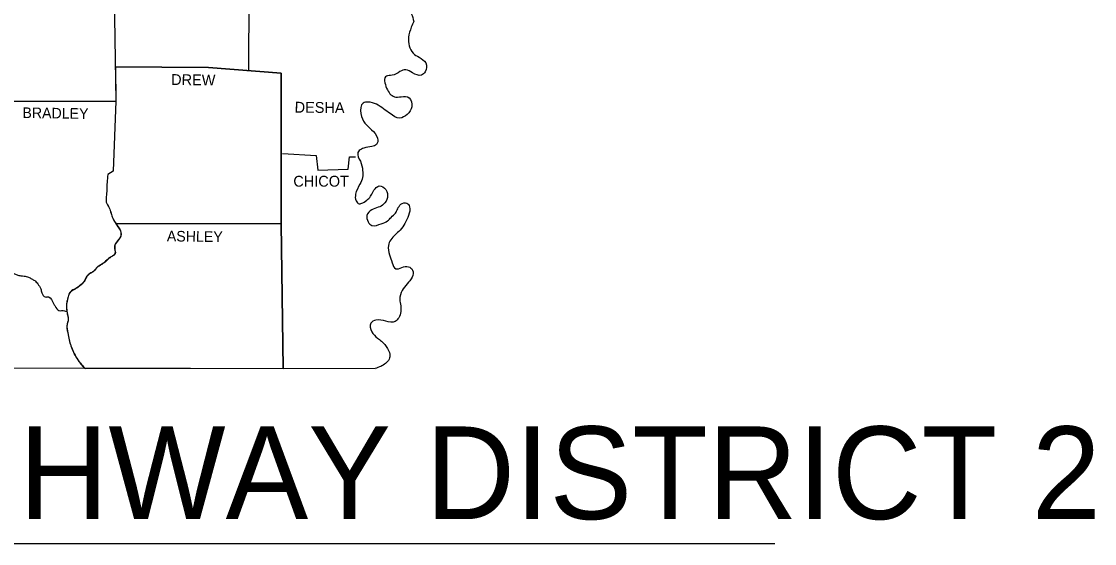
# Model space of a CAD drawing. Extents: x -42408 to 34530, y -43140 to 20491.
# Drawn here: x 9102 to 11234, y 6993 to 8031 of the extents above; entities that cross this region are included whole.
import ezdxf

# ---------------------------------------------------------------- set-up
doc = ezdxf.new("R2010")
doc.units = 0
for name, color, linetype in [('1', 7, 'Continuous'), ('2', 7, 'Continuous'), ('S_MISC_BOUNDARY', 7, 'Continuous')]:
    doc.layers.add(name, color=color, linetype=linetype)

msp = doc.modelspace()

# ---------------------------------------------------------------- linework, layer by layer
at = {"layer": '1'}
for points in [[(9297, 8143.5), (9297.5, 8080.9), (9286.9, 8080.4), (9289.9, 7872.6)], [(9635.4, 8116.9), (9629.4, 8103.4), (9602.9, 8100.9), (9601.4, 8082.9), (9553.8, 8082.9), (9553.3, 7933.2)], [(9288.4, 7940.7), (9474.2, 7939.2), (9618.4, 7928.2)], [(9618.4, 7928.2), (9618.4, 7628.8), (9622.4, 7340.9)], [(9063.6, 7872.1), (9289.9, 7872.6)], [(9289.9, 7872.6), (9284.9, 7733.4), (9273.9, 7726.4)], [(9620.9, 7768.5), (9688, 7764.4), (9691, 7735.4), (9751.6, 7737.4), (9754.1, 7761.9), (9765.6, 7761.9)], [(7969.2, 7748.9), (7970.2, 7343.9), (9805.1, 7340.9)], [(9293, 7629.3), (9618.4, 7629.3)]]:
    msp.add_lwpolyline(points, dxfattribs=at)
for points in [[(10226.7, 8693.2), (10215.2, 8678.7), (10198.2, 8687.7), (10198.2, 8699.7), (10200.7, 8712.2), (10194.7, 8720.2), (10184.1, 8716.7), (10184.1, 8701.2), (10183.1, 8686.2), (10180.1, 8664.6), (10187.1, 8658.1), (10203.2, 8656.1), (10214.7, 8653.1), (10221.7, 8641.6), (10221.2, 8627.6), (10215.7, 8614.1), (10207.7, 8603.1), (10195.2, 8599.1), (10185.1, 8605.6), (10181.1, 8618.6), (10176.6, 8630.1), (10168.1, 8638.6), (10159.1, 8629.1), (10157.1, 8611.6), (10157.6, 8596.6), (10157.6, 8576), (10170.6, 8562.5), (10178.6, 8547), (10176.1, 8533), (10166.6, 8516.5), (10162.6, 8501.9), (10158.6, 8482.4), (10159.1, 8460.9), (10155.6, 8439.8), (10148.6, 8425.8), (10135.6, 8414.3), (10127.1, 8406.8), (10120.1, 8399.3), (10116.6, 8384.3), (10114, 8373.8), (10104.5, 8361.2), (10097, 8360.2), (10091, 8365.3), (10089, 8373.8), (10089, 8382.3), (10085, 8390.8), (10072.5, 8394.3), (10062.5, 8393.8), (10058, 8386.8), (10064.5, 8367.3), (10067, 8354.7), (10063.5, 8337.7), (10065.5, 8335.7), (10047.5, 8326.2), (10032.9, 8324.7), (10020.9, 8321.2), (10009.4, 8313.7), (10003.9, 8302.7), (9995.9, 8293.7), (9988.9, 8285.1), (9979.4, 8281.1), (9968.9, 8283.1), (9954.8, 8284.6), (9946.8, 8274.6), (9949.3, 8260.1), (9958.8, 8251.6), (9972.9, 8247.6), (9987.4, 8248.6), (10001.4, 8250.1), (10014.4, 8243.1), (10011.9, 8229.6), (9999.4, 8223.1), (9980.9, 8221.1), (9965.8, 8222.6), (9947.8, 8218.6), (9938.8, 8207), (9943.8, 8189.5), (9963.3, 8182.5), (9972.4, 8166), (9972.9, 8150.5), (9966.4, 8129.9), (9957.3, 8120.4), (9939.8, 8116.4), (9926.3, 8113.9), (9924.3, 8090.9), (9918.3, 8079.4), (9907.8, 8075.9), (9892.8, 8083.4), (9883.7, 8086.9), (9872.7, 8091.9), (9858.7, 8100.4), (9848.2, 8098.9), (9851.2, 8076.9), (9852.2, 8075.9), (9864.2, 8059.3), (9876.2, 8046.3), (9881.7, 8030.8)], [(9881.7, 8030.8), (9876.7, 8019.3), (9871.2, 7999.3), (9872.7, 7982.2), (9880.2, 7967.7), (9892.3, 7959.7), (9905.3, 7948.2), (9904.3, 7930.7), (9896.8, 7924.2), (9879.2, 7928.7), (9865.7, 7934.7), (9854.2, 7931.2), (9838.7, 7923.7), (9827.2, 7922.2), (9827.7, 7898.1), (9843.2, 7881.1), (9856.7, 7881.1), (9872.2, 7879.1), (9877.7, 7861.1), (9868.7, 7846.1), (9853.7, 7838.5), (9834.7, 7847.6), (9821.2, 7857.1), (9807.6, 7866.1), (9790.6, 7870.6), (9781.1, 7868.6), (9776.6, 7847.6), (9784.6, 7828.5), (9797.6, 7815.5), (9809.6, 7798.5), (9807.6, 7786), (9798.6, 7782.5), (9782.6, 7779), (9773.1, 7774), (9770.6, 7770), (9775.6, 7752.9), (9780.1, 7734.4), (9780.1, 7720.4), (9774.6, 7707.4), (9766.1, 7687.3), (9767.1, 7674.3), (9773.1, 7668.3), (9780.6, 7670.3), (9790.6, 7677.3), (9797.1, 7685.3), (9802.6, 7695.4), (9813.1, 7703.9), (9826.2, 7696.4), (9829.2, 7680.8), (9821.7, 7667.3), (9811.1, 7661.3), (9798.1, 7656.3), (9788.6, 7645.3), (9791.1, 7632.3), (9798.6, 7625.3), (9817.2, 7628.8), (9829.7, 7634.3), (9836.7, 7641.3), (9845.2, 7649.8), (9849.7, 7658.3), (9856.2, 7667.3), (9867.7, 7669.8), (9873.2, 7662.3), (9871.2, 7645.3), (9864.2, 7629.3), (9854.7, 7615.8), (9844.2, 7606.2), (9831.2, 7585.7), (9833.7, 7566.7), (9838.7, 7551.2), (9845.7, 7539.1), (9857.7, 7541.7), (9871.2, 7543.2), (9879.2, 7536.6), (9878.2, 7522.6), (9868.2, 7509.1), (9858.7, 7496.1), (9853.7, 7478.1), (9855.7, 7465.6), (9855.7, 7454), (9851.7, 7441.5), (9844.7, 7434.5), (9826.2, 7435), (9806.6, 7437), (9796.1, 7431), (9798.1, 7414), (9809.6, 7401.5), (9817.7, 7395), (9829.2, 7380.9), (9834.2, 7369.4), (9832.7, 7359.4), (9825.7, 7350.9), (9805.1, 7340.9)], [(9273.9, 7726.4), (9272.4, 7710.9), (9271.9, 7696.4), (9270.9, 7682.3), (9270.9, 7671.8), (9276.9, 7660.3), (9280.4, 7649.3), (9283.9, 7639.8), (9290.9, 7627.3), (9297.5, 7617.8), (9299.5, 7604.2), (9295.5, 7597.2), (9287.9, 7586.7), (9287.4, 7567.7), (9278.4, 7561.7), (9266.9, 7551.7), (9260.4, 7547.2), (9253.4, 7542.7), (9245.9, 7534.6), (9234.9, 7527.1), (9226.9, 7514.6), (9217.9, 7505.1), (9210.3, 7500.1), (9199.8, 7493.6), (9195.3, 7483.6), (9191.8, 7465), (9193.3, 7451.5), (9195.3, 7439.5), (9192.8, 7424.5), (9195.3, 7408), (9197.8, 7395), (9201.8, 7383.4), (9207.3, 7370.4), (9214.3, 7358.4), (9229.4, 7339.9)], [(8774.8, 7610.7), (8782.8, 7616.3), (8790.3, 7619.3), (8797.8, 7617.8), (8805.8, 7616.8), (8812.8, 7617.8), (8821.8, 7616.3), (8829.3, 7611.7), (8837.8, 7608.2), (8846.4, 7608.2), (8853.9, 7608.2), (8860.4, 7603.7), (8872.4, 7604.2), (8882.4, 7608.2), (8892.4, 7611.2), (8905.9, 7612.7), (8918, 7604.2), (8926.5, 7597.2), (8933.5, 7589.2), (8938.5, 7580.2), (8944, 7575.2), (8953, 7571.7), (8960, 7570.2), (8968.5, 7567.7), (8973, 7565.7), (8977, 7556.2), (8983.5, 7543.2), (8996.1, 7538.6), (9011.6, 7544.7), (9024.1, 7548.2), (9033.1, 7551.2), (9038.6, 7553.2), (9043.6, 7553.7), (9042.1, 7554.7), (9048.1, 7556.2), (9053.6, 7552.2), (9057.1, 7546.7), (9063.1, 7538.6), (9068.7, 7531.6), (9074.2, 7529.1), (9079.7, 7532.1), (9087.2, 7529.6), (9093.7, 7527.1), (9101.2, 7525.1), (9107.7, 7524.6), (9116.2, 7522.6), (9122.7, 7519.1), (9128.7, 7515.6), (9134.7, 7509.1), (9140.7, 7499.1), (9142.8, 7491.1), (9149.8, 7483.1), (9156.3, 7483.1), (9165.8, 7470.1), (9169.3, 7465), (9176.8, 7456), (9182.3, 7456), (9192.8, 7454)]]:
    msp.add_spline(points, degree=3, dxfattribs=at)
at = {"layer": '2'}
msp.add_line((7249.3, 6992.9), (10598.6, 6992.9), dxfattribs=at)
at = {"layer": 'S_MISC_BOUNDARY'}
for p, q in [((9289, 7940.7), (9289.9, 7872.6)), ((9618.4, 7629.3), (9618.4, 7928.2)), ((9289.7, 7629.3), (9618.4, 7629.3)), ((9618.4, 7628.8), (9289.7, 7628.8)), ((9622.4, 7340.7), (9618.4, 7628.8)), ((9227.5, 7341.3), (9622.4, 7340.7))]:
    msp.add_line(p, q, dxfattribs=at)
for points in [[(9618.4, 7928.2), (9474.2, 7939.2), (9289, 7940.7)], [(9289.9, 7872.6), (9284.9, 7733.4), (9273.9, 7726.4)]]:
    msp.add_lwpolyline(points, dxfattribs=at)
for points in [[(9273.9, 7726.4), (9272.4, 7710.9), (9271.9, 7696.4), (9270.9, 7682.3), (9270.6, 7677.1), (9270.7, 7674.4), (9270.9, 7671.8), (9271.9, 7668.8), (9273.6, 7666), (9275.5, 7663.2), (9276.9, 7660.3), (9280.4, 7649.3), (9283.9, 7639.8), (9289.7, 7629.3)], [(9289.7, 7628.8), (9291, 7626.8), (9292.5, 7624.4), (9294.2, 7622), (9295.9, 7619.7), (9297.5, 7617.3), (9300, 7610.5), (9300.2, 7607), (9299.5, 7603.7), (9295.5, 7596.7), (9293.6, 7594), (9291.7, 7591.4), (9289.8, 7588.9), (9288, 7586.2), (9287.1, 7581.6), (9288.2, 7576.4), (9289, 7571.3), (9287.5, 7567.2), (9286.4, 7566.3), (9285.3, 7565.5), (9283, 7564.1), (9280.6, 7562.7), (9278.4, 7561.2), (9272.8, 7556.1), (9269.9, 7553.5), (9266.9, 7551.2), (9260.4, 7546.7), (9253.4, 7542.2), (9251.3, 7540.4), (9249.9, 7538.8)], [(9249.9, 7538.8), (9249.5, 7538.3), (9247.8, 7536.1), (9245.9, 7534.1), (9243.2, 7532.2), (9240.3, 7530.5), (9237.4, 7528.8), (9234.9, 7526.6), (9232.6, 7523.7), (9230.8, 7520.5), (9229, 7517.2), (9226.9, 7514.1), (9224.8, 7511.6), (9222.7, 7509.1), (9217.9, 7504.6), (9210.3, 7499.6), (9207.7, 7498), (9205.1, 7496.5), (9201.1, 7494), (9199.8, 7493.1), (9198, 7491), (9196.8, 7488.6), (9195.3, 7483.1), (9194, 7478.5), (9192.8, 7473.8), (9192, 7469.2), (9191.8, 7464.5), (9192.4, 7457.8), (9193.3, 7451), (9193.8, 7447.9)], [(9193.8, 7447.9), (9195.3, 7439), (9195.1, 7435.3), (9194.1, 7431.5), (9193, 7427.7), (9192.8, 7424), (9195.3, 7407.5), (9197.8, 7394.5), (9201.8, 7382.9), (9207.3, 7369.9), (9210.6, 7363.8), (9214.4, 7357.9), (9220.6, 7349.4), (9227.5, 7341.3)]]:
    msp.add_spline(points, degree=3, dxfattribs=at)

# ---------------------------------------------------------------- texts
at = {"layer": '2'}
for s, height, rotation, p in [('DREW', 21.52, 359.2258, (9399.6, 7904.6)), ('DESHA', 21.52, 359.3704, (9644.9, 7849.6)), ('BRADLEY', 21.02, 359.1449, (9104.2, 7839)), ('ASHLEY', 21.03, 359.2361, (9391.1, 7593.7))]:
    msp.add_text(s, height=height, rotation=rotation, dxfattribs=at).set_placement(p)
for s, height, p in [('CHICOT', 21.53, (9642.4, 7702.4)), ('ARKANSAS HIGHWAY DISTRICT 2', 184.218, (7249.3, 7041.5))]:
    msp.add_text(s, height=height, dxfattribs=at).set_placement(p)

doc.saveas('drawing.dxf')
